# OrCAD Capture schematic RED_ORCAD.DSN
size A
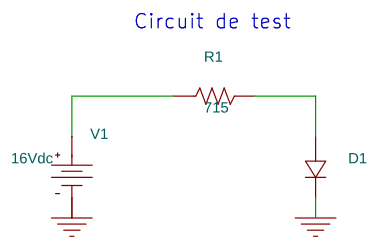
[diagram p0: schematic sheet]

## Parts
D1  Dbreak
R1  715  [AX/RC05]
V1  VDC

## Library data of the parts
D1 = Dbreak
R1 = R
V1 = VDC: DC: 16Vdc

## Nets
0: D1.1(2) V1.1(-)
N00092: R1.1 V1.0(+)
N00099: D1.0(1) R1.2

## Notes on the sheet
- Circuit de test
